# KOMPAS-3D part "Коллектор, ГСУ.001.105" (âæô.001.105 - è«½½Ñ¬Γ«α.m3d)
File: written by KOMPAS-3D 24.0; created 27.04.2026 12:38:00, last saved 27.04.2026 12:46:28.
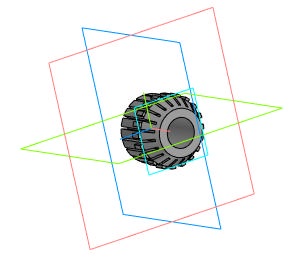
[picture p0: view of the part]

Document properties: Автор: User7; Полное имя файла: C:\Users\User7\Desktop\Двигатель мясорубки\ГСУ.001.105 - Коллектор.m3d

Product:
- Part/product: Коллектор  | designation ГСУ.001.105
    Масса: 0.01991

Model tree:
1. Эскиз:1
2. Элемент выдавливания:1
     Расстояние 1 = 10
3. Элемент выдавливания:2  (with: Грань.Элемент выдавливания:1)
     Расстояние 1 = 5; Смещение 1 = 15; Угол 1 = 28
4. Эскиз:2  (with: Грань.Элемент выдавливания:2)
5. Элемент выдавливания:3  (with: Грань.Элемент выдавливания:1)
     Расстояние 2 = 15
6. Массив по концентрической сетке:1  (with: Элемент выдавливания:3, Эскиз:2, Грань.Элемент выдавливания:1)  (20 pattern instances)
     Шаг 2 = 360
7. Смещенная плоскость:1  (with: Грань.Элемент выдавливания:1)
     Расстояние = 10
8. Эскиз:3  (with: Ребро.Элемент выдавливания:2)
9. Элемент выдавливания:4
     Расстояние 2 = 3
10. Массив по концентрической сетке:2  (with: Элемент выдавливания:4, Смещенная плоскость:1, Эскиз:3, Грань.Элемент выдавливания:1)  (20 pattern instances)
     Шаг 2 = 360
11. Эскиз:4  (with: Грань.Элемент выдавливания:1, Ребро.Элемент выдавливания:3)
12. Элемент выдавливания:5
     Расстояние 1 = 0.5
13. Фаска:1  (with: Ребро.Элемент выдавливания:5)
     Угол = 45; Длина 1 = 0.5; Длина 2 = 0.5
14. Эскиз:5  (with: Грань.Элемент выдавливания:2)
15. Элемент выдавливания:6

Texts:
  ГСУ.001.105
